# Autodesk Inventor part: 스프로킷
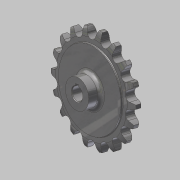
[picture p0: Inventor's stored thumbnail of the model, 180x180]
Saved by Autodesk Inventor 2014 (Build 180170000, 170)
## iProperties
Created: 2016-03
Part Number: 스프로킷
Material: 강철, 탄소
Document SubType Name: Modeling
Designer: mduedu
Density: 7.87 g/cm^3
Mass: 301.873 g
Surface Area: 120.622 cm^2
Volume: 38.3574 cm^3
Appearance: 반광택
Author: mduedu
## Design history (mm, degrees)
sketch "스케치1"
  geometry: L1 (0, 5)-(29.5, 5); L2 (29.5, 5)-(29.5, 4.1); L3 (30, 3.6)-(33.625, 3.6); L4 (40, 2)-(40, 0); L5 (40, 0)-(0, 0); L6 (0, 0)-(0, 5); L7 (0, -5)-(29.5, -5); L8 (29.5, -5)-(29.5, -4.1); L9 (30, -3.6)-(33.625, -3.6); L10 (40, -2)-(40, 0); L11 (0, 0)-(0, -5); A1 r 13.5 centre (33.625, -9.9) between (40, 2) and (33.625, 3.6); A2 r 13.5 centre (33.625, 9.9) between (33.625, -3.6) and (40, -2); A3 r 0.5 centre (30, 4.1) between (29.5, 4.1) and (30, 3.6); A4 r 0.5 centre (30, -4.1) between (30, -3.6) and (29.5, -4.1); 2 further points
  constraints: 22 end point, 8 point on circle, 6 symmetric about line, 5 tangent, 4 centre point, 4 parallel, 4 point on line, 1 equal radius, 1 horizontal, 1 perpendicular, 1 other
  dimensions: "d0" = 80 diameter of L4 L6; "d2" = 59 diameter of L2 L6; "d3" = 1.6 vertical distance of L4.start L3.end; "d4" = 3.6 distance from line of L4.end L3; "d5" = 5 distance between parallel lines of L5 L1; "d6" = 13.5 radius of A1; "d15" = 0.5 radius of A3
revolve "회전1" sketch "스케치1" stored, may be unused: angle "d7" = 90 deg
sketch "스케치2" dims "d8" = 65.2, "d11" = 80
  geometry: L1 (0, 0)-(0, 32.6); A1 r 36.57 centre (0, 0) between (-16.231, 32.771) and (0, 36.57); A2 r 3.97 centre (0, 36.57) between (-3.866, 35.665) and (0, 32.6); A3 r 12.7 centre (-16.231, 32.771) between (-3.866, 35.665) and (-5.534, 39.615); A4 r 12.7 centre (16.231, 32.771) between (5.534, 39.615) and (3.866, 35.665); A5 r 3.97 centre (0, 36.57) between (0, 32.6) and (3.866, 35.665); A6 r 40 centre (0, 0) between (5.534, 39.615) and (-5.534, 39.615); 2 further points
  constraints: 12 point on circle, 6 centre point, 4 coincident, 3 symmetric about line, 2 end point, 1 point on line, 1 tangent, 1 vertical, 1 vertical alignment, 7 other
  dimensions: "d10" = 73.14 diameter of A1; "d12" = 12.7 radius of A3
extrude "돌출1" cut sketch "스케치2" stored distance "d13" = 10; taper "d14" = 0 deg
sketch "스케치3"
  geometry: C1 r 11 at (0, 0); 1 further point
  constraints: 1 centre point, 1 coincident
  dimensions: "d19" = 22 diameter of C1
extrude "돌출2" join sketch "스케치3" distance "d20" = 10; taper "d21" = 0 deg
fillet "모깎기1" dims "d22" = 3
sketch "스케치4"
  geometry: L1 (-1.5, 0)-(1.5, 0); L2 (1.5, 0)-(1.5, 6.4); L3 (1.5, 6.4)-(-1.5, 6.4); L4 (-1.5, 6.4)-(-1.5, 0); C1 r 5 at (0, 0); 2 further points
  constraints: 8 end point, 2 coincident, 2 parallel, 1 centre point, 1 horizontal, 1 midpoint, 1 perpendicular
  dimensions: "d23" = 10 diameter of C1; "d25" = 3 distance of L2.end L3.end; "d26" = 6.4 distance of L1.end L2.end
extrude "돌출3" cut sketch "스케치4" stored distance "d27" = 8; taper "d28" = 0 deg
chamfer "모따기1" distance "d29" = 0.5; stored, may be unused: second distance "d30" = 2, angle "d31" = 45 deg
sketch "스케치5" dims "d33" = 50
  geometry: C1 r 1 at (0, 25); 2 further points
  constraints: 2 vertical alignment, 1 centre point, 1 coincident, 2 other
  dimensions: "d32" = 2 diameter of C1
extrude "돌출4" join sketch "스케치5" distance "d34" = 0.5; taper "d35" = 0 deg
node "솔리드1"
pattern_circular "원형 패턴1" dims angle "d17" = 360 deg
